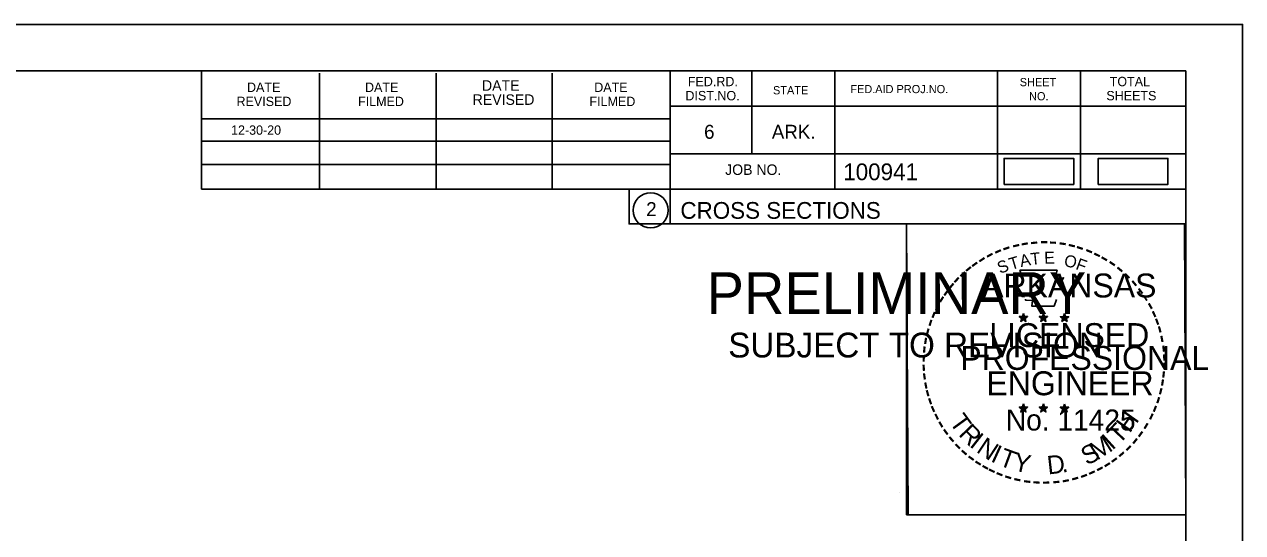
# Model space of a CAD drawing. Extents: x 1370538 to 1372872, y 376220 to 381127.
# Drawn here: x 1370769.7 to 1370871.5, y 376817.9 to 376860.4 of the extents above; entities that cross this region are included whole.
import ezdxf

# ---------------------------------------------------------------- set-up
doc = ezdxf.new("R2010")
doc.units = 0
for name, color, linetype in [('Default', 7, 'Continuous'), ('R_Border Notes', 7, 'Continuous'), ('R_No Plot', 7, 'Continuous'), ('T_Indications', 7, 'Continuous'), ('T_Notes', 7, 'Continuous')]:
    doc.layers.add(name, color=color, linetype=linetype)

msp = doc.modelspace()

# ---------------------------------------------------------------- linework, layer by layer
at = {"layer": 'Default'}
for points in [[(1370851.6, 376847.05), (1370857.43, 376847.05), (1370857.43, 376849.23), (1370851.6, 376849.23)], [(1370859.47, 376847.05), (1370865.3, 376847.05), (1370865.3, 376849.23), (1370859.47, 376849.23)]]:
    msp.add_lwpolyline(points, close=True, dxfattribs=at)
at = {"layer": 'R_Border Notes'}
for p, q in [((1370550.61, 376856.55), (1370866.79, 376856.55)), ((1370784.53, 376846.67), (1370784.53, 376856.55)), ((1370794.39, 376846.67), (1370794.39, 376856.35)), ((1370804.15, 376846.67), (1370804.15, 376856.35)), ((1370813.83, 376846.67), (1370813.83, 376856.35)), ((1370823.69, 376856.55), (1370823.69, 376843.75)), ((1370830.53, 376856.55), (1370830.53, 376849.61)), ((1370837.47, 376856.55), (1370837.47, 376846.67)), ((1370851.05, 376856.55), (1370851.05, 376846.67)), ((1370857.99, 376856.55), (1370857.99, 376846.67)), ((1370866.79, 376651.09), (1370866.79, 376856.55)), ((1370866.79, 376853.61), (1370823.69, 376853.61)), ((1370866.79, 376853.63), (1370866.79, 376853.63)), ((1370784.53, 376852.53), (1370823.69, 376852.53)), ((1370784.53, 376850.67), (1370823.69, 376850.67)), ((1370784.53, 376846.67), (1370784.53, 376848.73)), ((1370784.53, 376848.73), (1370823.69, 376848.73)), ((1370866.79, 376849.61), (1370823.69, 376849.61)), ((1370826.65, 376849.61), (1370866.79, 376849.61)), ((1370866.79, 376846.67), (1370784.53, 376846.67)), ((1370823.69, 376843.75), (1370866.79, 376843.75))]:
    msp.add_line(p, q, dxfattribs=at)
msp.add_circle((1370822.07, 376844.89), 1.47, dxfattribs=at)
at = {"layer": 'R_No Plot'}
for p, q in [((1370538.21, 376860.44), (1370871.54, 376860.44)), ((1370842.82, 376821.29), (1370842.82, 376821.29))]:
    msp.add_line(p, q, dxfattribs=at)
for points in [[(1370538.2, 376860.44), (1370871.54, 376860.44), (1370871.54, 376647.11), (1370538.2, 376647.11)], [(1370784.53, 376856.55), (1370784.53, 376846.67), (1370820.26, 376846.67), (1370820.26, 376843.75), (1370843.46, 376843.75), (1370843.46, 376819.42), (1370866.79, 376819.42), (1370866.79, 376651.09), (1370550.61, 376651.09), (1370550.61, 376856.55)], [(1370843.46, 376843.75), (1370866.67, 376843.75), (1370866.79, 376819.42), (1370843.58, 376819.42)]]:
    msp.add_lwpolyline(points, close=True, dxfattribs=at)
at = {"layer": 'T_Indications'}
for p, q in [((1370852.87, 376836.01), (1370853.22, 376835.89)), ((1370852.87, 376836.01), (1370853.12, 376835.96)), ((1370852.87, 376836.01), (1370853.11, 376835.88)), ((1370853, 376835.6), (1370853.22, 376835.89)), ((1370853, 376835.6), (1370853.13, 376835.84)), ((1370853, 376835.6), (1370853.22, 376835.81)), ((1370853.22, 376836.26), (1370853.18, 376836.01)), ((1370853.22, 376835.89), (1370853.22, 376836.26)), ((1370853.22, 376836.26), (1370853.27, 376836.01)), ((1370853.57, 376836.01), (1370853.22, 376835.89)), ((1370853.43, 376835.6), (1370853.22, 376835.89)), ((1370853.43, 376835.6), (1370853.22, 376835.81)), ((1370853.57, 376836.01), (1370853.28, 376835.96)), ((1370853.43, 376835.6), (1370853.3, 376835.89)), ((1370853.57, 376836.01), (1370853.36, 376835.9)), ((1370854.54, 376836.01), (1370854.89, 376835.89)), ((1370854.54, 376836.01), (1370854.79, 376835.96)), ((1370854.54, 376836.01), (1370854.78, 376835.88)), ((1370854.67, 376835.6), (1370854.89, 376835.89)), ((1370854.67, 376835.6), (1370854.8, 376835.84)), ((1370854.67, 376835.6), (1370854.89, 376835.81)), ((1370854.89, 376836.26), (1370854.85, 376836.01)), ((1370854.89, 376835.89), (1370854.89, 376836.26)), ((1370854.89, 376836.26), (1370854.94, 376836.01)), ((1370855.24, 376836.01), (1370854.89, 376835.89)), ((1370855.1, 376835.6), (1370854.89, 376835.89)), ((1370855.1, 376835.6), (1370854.89, 376835.81)), ((1370855.24, 376836.01), (1370854.95, 376835.96)), ((1370855.1, 376835.6), (1370854.97, 376835.89)), ((1370855.24, 376836.01), (1370855.03, 376835.9)), ((1370856.31, 376835.99), (1370856.65, 376835.88)), ((1370856.31, 376835.99), (1370856.56, 376835.95)), ((1370856.31, 376835.99), (1370856.54, 376835.87)), ((1370856.44, 376835.59), (1370856.65, 376835.88)), ((1370856.44, 376835.59), (1370856.56, 376835.83)), ((1370856.44, 376835.59), (1370856.65, 376835.8)), ((1370856.65, 376836.25), (1370856.61, 376836)), ((1370856.65, 376835.88), (1370856.65, 376836.25)), ((1370856.65, 376836.25), (1370856.7, 376836)), ((1370857, 376835.99), (1370856.65, 376835.88)), ((1370856.87, 376835.59), (1370856.65, 376835.88)), ((1370856.87, 376835.59), (1370856.65, 376835.8)), ((1370857, 376835.99), (1370856.72, 376835.94)), ((1370856.87, 376835.59), (1370856.73, 376835.88)), ((1370857, 376835.99), (1370856.8, 376835.89)), ((1370852.87, 376828.43), (1370853.22, 376828.32)), ((1370852.87, 376828.43), (1370853.12, 376828.39)), ((1370852.87, 376828.43), (1370853.1, 376828.31)), ((1370853.22, 376828.69), (1370853.18, 376828.43)), ((1370853.22, 376828.32), (1370853.22, 376828.69)), ((1370853.22, 376828.69), (1370853.27, 376828.44)), ((1370853.56, 376828.43), (1370853.22, 376828.32)), ((1370853.56, 376828.43), (1370853.28, 376828.38)), ((1370853.56, 376828.43), (1370853.36, 376828.33)), ((1370854.54, 376828.43), (1370854.89, 376828.32)), ((1370854.54, 376828.43), (1370854.79, 376828.39)), ((1370854.54, 376828.43), (1370854.77, 376828.31)), ((1370854.89, 376828.69), (1370854.84, 376828.43)), ((1370854.89, 376828.32), (1370854.89, 376828.69)), ((1370854.89, 376828.69), (1370854.93, 376828.44)), ((1370855.23, 376828.43), (1370854.89, 376828.32)), ((1370855.23, 376828.43), (1370854.95, 376828.38)), ((1370855.23, 376828.43), (1370855.03, 376828.33)), ((1370856.3, 376828.42), (1370856.65, 376828.31)), ((1370856.3, 376828.42), (1370856.56, 376828.38)), ((1370856.3, 376828.42), (1370856.54, 376828.3)), ((1370856.65, 376828.68), (1370856.61, 376828.42)), ((1370856.65, 376828.31), (1370856.65, 376828.68)), ((1370856.65, 376828.68), (1370856.7, 376828.43)), ((1370857, 376828.42), (1370856.65, 376828.31)), ((1370857, 376828.42), (1370856.71, 376828.37)), ((1370857, 376828.42), (1370856.8, 376828.32)), ((1370853, 376828.02), (1370853.22, 376828.32)), ((1370853, 376828.02), (1370853.13, 376828.27)), ((1370853, 376828.02), (1370853.21, 376828.24)), ((1370853.43, 376828.02), (1370853.21, 376828.24)), ((1370853.43, 376828.02), (1370853.22, 376828.32)), ((1370853.43, 376828.02), (1370853.29, 376828.32)), ((1370854.67, 376828.02), (1370854.89, 376828.32)), ((1370854.67, 376828.02), (1370854.8, 376828.27)), ((1370854.67, 376828.02), (1370854.88, 376828.24)), ((1370855.1, 376828.02), (1370854.88, 376828.24)), ((1370855.1, 376828.02), (1370854.89, 376828.32)), ((1370855.1, 376828.02), (1370854.96, 376828.32)), ((1370856.44, 376828.01), (1370856.65, 376828.31)), ((1370856.44, 376828.01), (1370856.56, 376828.26)), ((1370856.44, 376828.01), (1370856.65, 376828.23)), ((1370856.87, 376828.01), (1370856.65, 376828.31)), ((1370856.87, 376828.01), (1370856.65, 376828.23)), ((1370856.87, 376828.01), (1370856.73, 376828.31))]:
    msp.add_line(p, q, dxfattribs=at)
for points in [[(1370852.91, 376839.88), (1370853.18, 376839.06)], [(1370856.42, 376838.96), (1370856.57, 376839.25), (1370855.88, 376839.22), (1370856.03, 376839.88), (1370852.91, 376839.88)], [(1370853.4, 376837.46), (1370853.4, 376837.37), (1370853.97, 376837.35), (1370853.91, 376836.88), (1370855.78, 376836.88), (1370855.98, 376837.42)], [(1370853.22, 376836.26), (1370853.43, 376835.6), (1370852.87, 376836.01), (1370853.57, 376836.01), (1370853, 376835.6), (1370853.22, 376836.26)], [(1370854.89, 376836.26), (1370855.1, 376835.6), (1370854.54, 376836.01), (1370855.24, 376836.01), (1370854.67, 376835.6), (1370854.89, 376836.26)], [(1370856.65, 376836.25), (1370856.87, 376835.59), (1370856.31, 376835.99), (1370857, 376835.99), (1370856.44, 376835.59), (1370856.65, 376836.25)], [(1370853.22, 376828.69), (1370853.43, 376828.02), (1370852.87, 376828.43), (1370853.56, 376828.43), (1370853, 376828.02), (1370853.22, 376828.69)], [(1370854.89, 376828.69), (1370855.1, 376828.02), (1370854.54, 376828.43), (1370855.23, 376828.43), (1370854.67, 376828.02), (1370854.89, 376828.69)], [(1370856.65, 376828.68), (1370856.87, 376828.01), (1370856.3, 376828.42), (1370857, 376828.42), (1370856.44, 376828.01), (1370856.65, 376828.68)]]:
    msp.add_lwpolyline(points, dxfattribs=at)
for centre, radius in [((1370853.22, 376835.89), 0.172), ((1370853.22, 376835.89), 0.145), ((1370853.22, 376835.89), 0.116), ((1370853.22, 376835.89), 0.0991), ((1370853.22, 376835.89), 0.0747), ((1370853.22, 376835.89), 0.0495), ((1370853.22, 376835.89), 0.0296), ((1370854.89, 376835.89), 0.172), ((1370854.89, 376835.89), 0.145), ((1370854.89, 376835.89), 0.116), ((1370854.89, 376835.89), 0.0991), ((1370854.89, 376835.89), 0.0747), ((1370854.89, 376835.89), 0.0495), ((1370854.89, 376835.89), 0.0296), ((1370856.65, 376835.88), 0.172), ((1370856.65, 376835.88), 0.145), ((1370856.65, 376835.88), 0.116), ((1370856.65, 376835.88), 0.0991), ((1370856.65, 376835.88), 0.0747), ((1370856.65, 376835.88), 0.0495), ((1370856.65, 376835.88), 0.0296), ((1370853.22, 376828.32), 0.172), ((1370853.22, 376828.32), 0.145), ((1370853.22, 376828.32), 0.116), ((1370853.22, 376828.32), 0.0991), ((1370853.22, 376828.32), 0.0747), ((1370853.22, 376828.32), 0.0495), ((1370853.22, 376828.32), 0.0296), ((1370854.88, 376828.32), 0.172), ((1370854.88, 376828.32), 0.145), ((1370854.88, 376828.32), 0.116), ((1370854.88, 376828.32), 0.0991), ((1370854.88, 376828.32), 0.0747), ((1370854.88, 376828.32), 0.0495), ((1370854.88, 376828.32), 0.0296), ((1370856.65, 376828.31), 0.172), ((1370856.65, 376828.31), 0.145), ((1370856.65, 376828.31), 0.116), ((1370856.65, 376828.31), 0.0991), ((1370856.65, 376828.31), 0.0747), ((1370856.65, 376828.31), 0.0495), ((1370856.65, 376828.31), 0.0296)]:
    msp.add_circle(centre, radius, dxfattribs=at)

# ---------------------------------------------------------------- texts
at = {"layer": 'R_Border Notes'}
for s, height, p in [('FED.RD.', 0.782, (1370825.17, 376855.27)), ('SHEET', 0.684, (1370852.91, 376855.27)), ('TOTAL', 0.782, (1370860.43, 376855.27)), ('DATE', 0.782, (1370788.33, 376854.79)), ('DATE', 0.782, (1370798.19, 376854.79)), ('DATE', 0.879, (1370807.97, 376854.89)), ('DATE', 0.782, (1370817.35, 376854.79)), ('DIST.NO.', 0.782, (1370824.97, 376854.09)), ('STATE', 0.684, (1370832.29, 376854.59)), ('FED.AID PROJ.NO.', 0.684, (1370838.75, 376854.69)), ('SHEETS', 0.782, (1370860.15, 376854.09)), ('REVISED', 0.782, (1370787.45, 376853.61)), ('FILMED', 0.782, (1370797.61, 376853.61)), ('REVISED', 0.879, (1370807.19, 376853.71)), ('FILMED', 0.782, (1370816.95, 376853.61)), ('NO.', 0.684, (1370853.69, 376854.09)), ('6', 1.17, (1370826.53, 376850.87)), ('ARK.', 1.172, (1370832.19, 376850.87)), ('JOB NO.', 0.879, (1370828.29, 376847.85)), ('100941', 1.4, (1370838.16, 376847.41)), ('2', 1.17, (1370821.69, 376844.4)), ('CROSS SECTIONS', 1.4, (1370824.55, 376844.18))]:
    msp.add_text(s, height=height, rotation=360, dxfattribs=at).set_placement(p)
msp.add_text('12-30-20', height=0.78, dxfattribs=at).set_placement((1370787, 376851.21))
at = {"layer": 'T_Indications'}
for s, height, rotation, p in [('-', 1.6, 24.3072, (1370851.03, 376840.74)), ('-', 1.6, 19.1761, (1370851.66, 376841.01)), ('-', 1.6, 13.6301, (1370852.41, 376841.25)), ('-', 1.6, 10.2193, (1370853.09, 376841.41)), ('-', 1.6, 5.8968, (1370853.82, 376841.52)), ('-', 1.6, 0.1862, (1370854.59, 376841.6)), ('-', 1.6, 357.743, (1370855.31, 376841.58)), ('-', 1.6, 352.1617, (1370856.06, 376841.53)), ('-', 1.6, 347.2049, (1370856.78, 376841.41)), ('-', 1.6, 342.3362, (1370857.41, 376841.26)), ('-', 1.6, 337.8551, (1370858.15, 376841.03)), ('-', 1.6, 36.2317, (1370849.22, 376839.66)), ('-', 1.6, 34.0636, (1370849.8, 376840.05)), ('-', 1.6, 28.7918, (1370850.39, 376840.42)), ('S', 1, 21.594, (1370851.27, 376839.56)), ('T', 1, 16.4036, (1370852.18, 376839.89)), ('A', 1, 11.2132, (1370853.01, 376840.14)), ('T', 1, 6.0228, (1370853.86, 376840.31)), ('E', 1, 0.8323, (1370854.96, 376840.42)), ('O', 1, 350.4515, (1370856.57, 376840.21)), ('F', 1, 340.0707, (1370857.52, 376839.98)), ('-', 1.6, 334.1211, (1370858.78, 376840.76)), ('-', 1.6, 329.6409, (1370859.36, 376840.48)), ('-', 1.6, 325.8627, (1370860, 376840.12)), ('-', 1.6, 42.9622, (1370848.31, 376838.86)), ('-', 1.6, 38.9507, (1370848.74, 376839.28)), ('ARKANSAS', 2, 360, (1370849.77, 376837.6)), ('-', 1.6, 320.5297, (1370860.61, 376839.69)), ('-', 1.6, 315.5786, (1370861.21, 376839.21)), ('-', 1.6, 50.6142, (1370847.46, 376837.9)), ('-', 1.6, 48.423, (1370847.86, 376838.39)), ('-', 1.6, 309.8797, (1370861.78, 376838.66)), ('-', 1.6, 58.0706, (1370846.72, 376836.81)), ('-', 1.6, 54.2325, (1370847.05, 376837.33)), ('-', 1.6, 306.6522, (1370862.3, 376838.05)), ('-', 1.4, 303.6753, (1370862.79, 376837.49)), ('-', 1.6, 62.8713, (1370846.41, 376836.19)), ('-', 1.6, 299.6684, (1370863.11, 376836.88)), ('-', 1.6, 72.3945, (1370845.93, 376834.95)), ('-', 1.6, 67.7743, (1370846.15, 376835.58)), ('LICENSED', 2, 360, (1370850.36, 376833.45)), ('DWB', 0.01, 360, (1370853.21, 376835.89)), ('DWB', 0.01, 360, (1370854.88, 376835.89)), ('DWB', 0.01, 360, (1370856.64, 376835.88)), ('-', 1.6, 294.6628, (1370863.43, 376836.27)), ('-', 1.6, 290.5728, (1370863.69, 376835.69)), ('-', 1.6, 75.461, (1370845.73, 376834.24)), ('-', 1.6, 285.1233, (1370863.92, 376835.11)), ('-', 1.6, 85.1863, (1370845.52, 376832.83)), ('-', 1.6, 81.2013, (1370845.6, 376833.52)), ('PROFESSIONAL', 2, 360, (1370847.94, 376831.54)), ('-', 1.6, 280.5493, (1370864.12, 376834.37)), ('-', 1.6, 276.5962, (1370864.28, 376833.6)), ('-', 1.6, 89.0622, (1370845.5, 376832.13)), ('-', 1.6, 274.3301, (1370864.34, 376832.88)), ('-', 1.6, 94.1959, (1370845.53, 376831.41)), ('ENGINEER', 2, 360, (1370850.13, 376829.42)), ('-', 1.6, 263.5172, (1370864.36, 376831.58)), ('-', 1.6, 269.9407, (1370864.38, 376832.25)), ('-', 1.6, 98.9479, (1370845.61, 376830.74)), ('-', 1.6, 101.7149, (1370845.74, 376830.01)), ('-', 1.6, 260.9953, (1370864.29, 376830.93)), ('-', 1.6, 105.4578, (1370845.9, 376829.41)), ('-', 1.6, 255.7626, (1370864.18, 376830.25)), ('-', 1.6, 109.0874, (1370846.12, 376828.78)), ('-', 1.6, 114.0643, (1370846.37, 376828.19)), ('-', 1.6, 247.8887, (1370863.77, 376828.85)), ('-', 1.6, 252.8681, (1370864, 376829.53)), ('-', 1.6, 115.7289, (1370846.68, 376827.57)), ('T', 1.54, 306.0406, (1370846.98, 376827.16)), ('No. 11425', 1.757, 360, (1370851.75, 376826.47)), ('DWB', 0.01, 360, (1370853.2, 376828.32)), ('DWB', 0.01, 360, (1370854.87, 376828.32)), ('DWB', 0.01, 360, (1370856.64, 376828.31)), ('H', 1.54, 54.6088, (1370862.1, 376826.19)), ('-', 1.6, 244.6197, (1370863.51, 376828.23)), ('-', 1.6, 120.4471, (1370847.03, 376826.98)), ('-', 1.6, 125.8934, (1370847.44, 376826.42)), ('R', 1.54, 314.005, (1370847.74, 376826.11)), ('T', 1.54, 46.6444, (1370861.21, 376825.25)), ('-', 1.6, 233.8452, (1370862.72, 376826.82)), ('-', 1.6, 239.0712, (1370863.12, 376827.47)), ('-', 1.6, 130.7181, (1370847.9, 376825.87)), ('-', 1.6, 134.2238, (1370848.42, 376825.32)), ('I', 1.54, 321.9694, (1370848.64, 376825.18)), ('N', 1.54, 326.5002, (1370849.21, 376824.71)), ('S', 1.54, 26.9312, (1370858.52, 376823.52)), ('M', 1.54, 32.6563, (1370859.36, 376823.93)), ('I', 1.54, 42.1136, (1370860.64, 376824.77)), ('-', 1.6, 231.2538, (1370862.29, 376826.25)), ('-', 1.6, 138.9338, (1370848.94, 376824.86)), ('-', 1.6, 144.6463, (1370849.5, 376824.45)), ('I', 1.54, 335.3603, (1370850.41, 376823.92)), ('T', 1.54, 339.8912, (1370851.08, 376823.59)), ('Y', 1.54, 347.8556, (1370852.29, 376823.15)), ('D', 1.54, 6.3969, (1370855.28, 376822.79)), ('-', 1.6, 221.0851, (1370861.28, 376825.18)), ('-', 1.6, 225.7653, (1370861.81, 376825.69)), ('-', 1.6, 148.0898, (1370850.06, 376824.08)), ('-', 1.6, 151.5704, (1370850.64, 376823.76)), ('-', 1.6, 154.6002, (1370851.16, 376823.51)), ('-', 1.6, 207.3568, (1370859.64, 376823.98)), ('-', 1.6, 212.2491, (1370860.2, 376824.32)), ('-', 1.6, 215.7363, (1370860.74, 376824.71)), ('-', 1.6, 158.5612, (1370851.78, 376823.26)), ('-', 1.6, 162.7983, (1370852.47, 376823.04)), ('-', 1.6, 167.5555, (1370853.19, 376822.88)), ('-', 1.6, 173.1155, (1370853.96, 376822.77)), ('-', 1.6, 176.5183, (1370854.71, 376822.72)), ('-', 1.6, 185.8167, (1370856.26, 376822.81)), ('-', 1.6, 191.2858, (1370856.99, 376822.94)), ('.', 1.54, 13.7642, (1370856.47, 376822.92)), ('-', 1.6, 195.4743, (1370857.72, 376823.14)), ('-', 1.6, 200.7184, (1370858.4, 376823.38)), ('-', 1.6, 204.2516, (1370859.02, 376823.66)), ('-', 1.6, 181.5918, (1370855.45, 376822.74))]:
    msp.add_text(s, height=height, rotation=rotation, dxfattribs=at).set_placement(p)
at = {"layer": 'T_Notes'}
for s, height, p in [('PRELIMINARY', 3.5, (1370826.74, 376836.21)), ('DWB', 0.01, (1370827.48, 376838.06)), ('SUBJECT TO REVISION', 2.0751, (1370828.55, 376832.58))]:
    msp.add_text(s, height=height, rotation=360, dxfattribs=at).set_placement(p)

doc.saveas('drawing.dxf')
